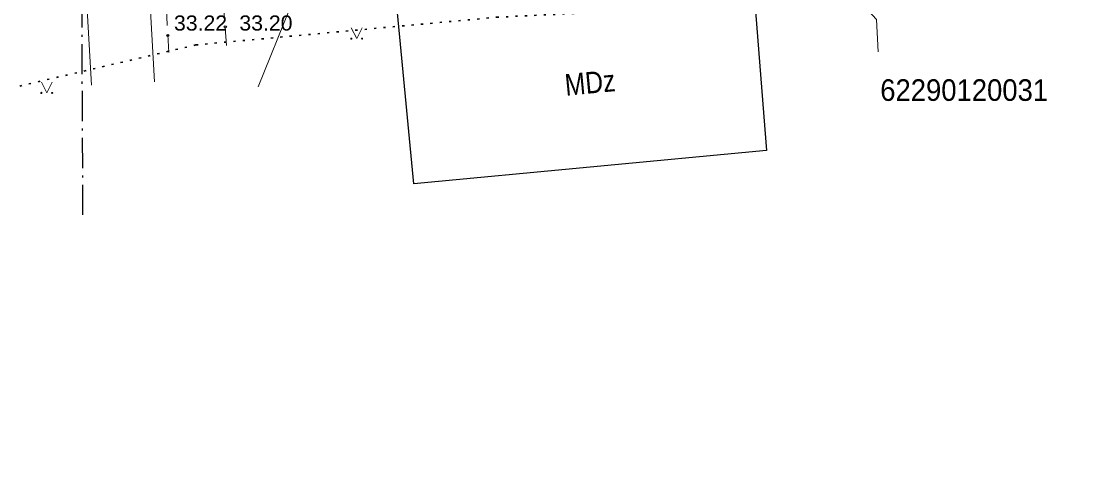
# Model space of a CAD drawing. Extents: x 380758 to 381729, y 283236 to 283533.
# Drawn here: x 381234.95 to 381283.7, y 283306.61 to 283327.96 of the extents above; entities that cross this region are included whole.
import ezdxf

# ---------------------------------------------------------------- set-up
doc = ezdxf.new("R2010")
doc.units = 0
doc.header["$LTSCALE"] = 0.28
for name, pattern in [('DOT_DASHED', [7.7, 5, -1.2, 0.3, -1.2]), ('DOTTED', [1.5, 0.3, -1.2]), ('MEDIUM_DASHED', [4.5, 3, -1.5])]:
    doc.linetypes.add(name, pattern=pattern)
for name, color, linetype, lineweight in [('23', 7, 'Continuous', 13), ('25', 7, 'DOTTED', 35), ('29', 7, 'DOT_DASHED', 25), ('37', 7, 'MEDIUM_DASHED', 13), ('39', 7, 'Continuous', 13), ('4', 7, 'Continuous', 13), ('40', 7, 'Continuous', 25), ('58', 7, 'Continuous', 25), ('7', 7, 'Continuous', 13)]:
    doc.layers.add(name, color=color, linetype=linetype, lineweight=lineweight)
doc.layers.add('59', color=7, linetype='Continuous')

msp = doc.modelspace()

# ---------------------------------------------------------------- linework, layer by layer
at = {"layer": '23'}
for points in [[(381250.241, 283327.648), (381250.491, 283327.148), (381250.741, 283327.648)], [(381235.892, 283325.134), (381236.142, 283324.634), (381236.392, 283325.134)]]:
    msp.add_lwpolyline(points, dxfattribs=at)
for centre, radius in [((381250.2404, 283327.1479), 0.028), ((381250.7404, 283327.1479), 0.0263), ((381235.8919, 283324.634), 0.028), ((381236.3919, 283324.634), 0.0263)]:
    msp.add_circle(centre, radius, dxfattribs=at)
at = {"layer": '25'}
msp.add_lwpolyline([(380965.254, 283306.611), (380999.033, 283308.647), (381050.794, 283310.677), (381081.859, 283313.257), (381112.788, 283315.836), (381135.685, 283318.987), (381169.311, 283321.878), (381185.52, 283321.507), (381211.031, 283321.569), (381227.246, 283323.167), (381243.045, 283326.858), (381256.971, 283328.14), (381276.827, 283329.124), (381289.49, 283330.785), (381296.806, 283333.369), (381324.562, 283332.372), (381358.23, 283334.462), (381389.309, 283326.777)], dxfattribs=at)
at = {"layer": '29'}
msp.add_line((381237.816, 283318.98), (381237.723, 283338.177), dxfattribs=at)
at = {"layer": '37'}
msp.add_line((381241.787, 283326.505), (381241.214, 283337.574), dxfattribs=at)
msp.add_lwpolyline([(381241.214, 283337.574), (381243.646, 283337.721), (381244.482, 283326.645)], dxfattribs=at)
at = {"layer": '39'}
msp.add_line((381237.474, 283338.16), (381238.205, 283324.987), dxfattribs=at)
msp.add_lwpolyline([(381237.474, 283338.16), (381240.392, 283338.322), (381241.123, 283325.149)], dxfattribs=at)
at = {"layer": '40'}
msp.add_lwpolyline([(381252.318, 283329.008), (381268.784, 283330.577), (381269.471, 283321.973), (381253.137, 283320.417)], close=True, dxfattribs=at)
at = {"layer": '58'}
for centre in [(381244.403, 283327.6951), (381241.746, 283327.2941)]:
    msp.add_circle(centre, 0.0534, dxfattribs=at)
at = {"layer": '7'}
for points in [[(381270.038, 283332.941), (381274.555, 283328.042), (381274.637, 283326.53)], [(381268.571, 283331.826), (381249.804, 283330.374), (381247.431, 283328.627), (381245.932, 283324.916)]]:
    msp.add_lwpolyline(points, dxfattribs=at)

# ---------------------------------------------------------------- texts
at = {"layer": '4', "width": 0.85}
msp.add_text('MDz', height=1, rotation=5.443, dxfattribs=at).set_placement((381260.177, 283324.499))
at = {"layer": '58', "width": 1.05}
for s, p in [('33.22', (381242.031, 283327.522)), ('33.20', (381245.058, 283327.523))]:
    msp.add_text(s, height=0.7, dxfattribs=at).set_placement(p)
at = {"layer": '59', "width": 0.95}
msp.add_text('62290120031', height=1, dxfattribs=at).set_placement((381274.73, 283324.266))

doc.saveas('drawing.dxf')
